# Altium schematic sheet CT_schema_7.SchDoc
size 366 x 245 mm
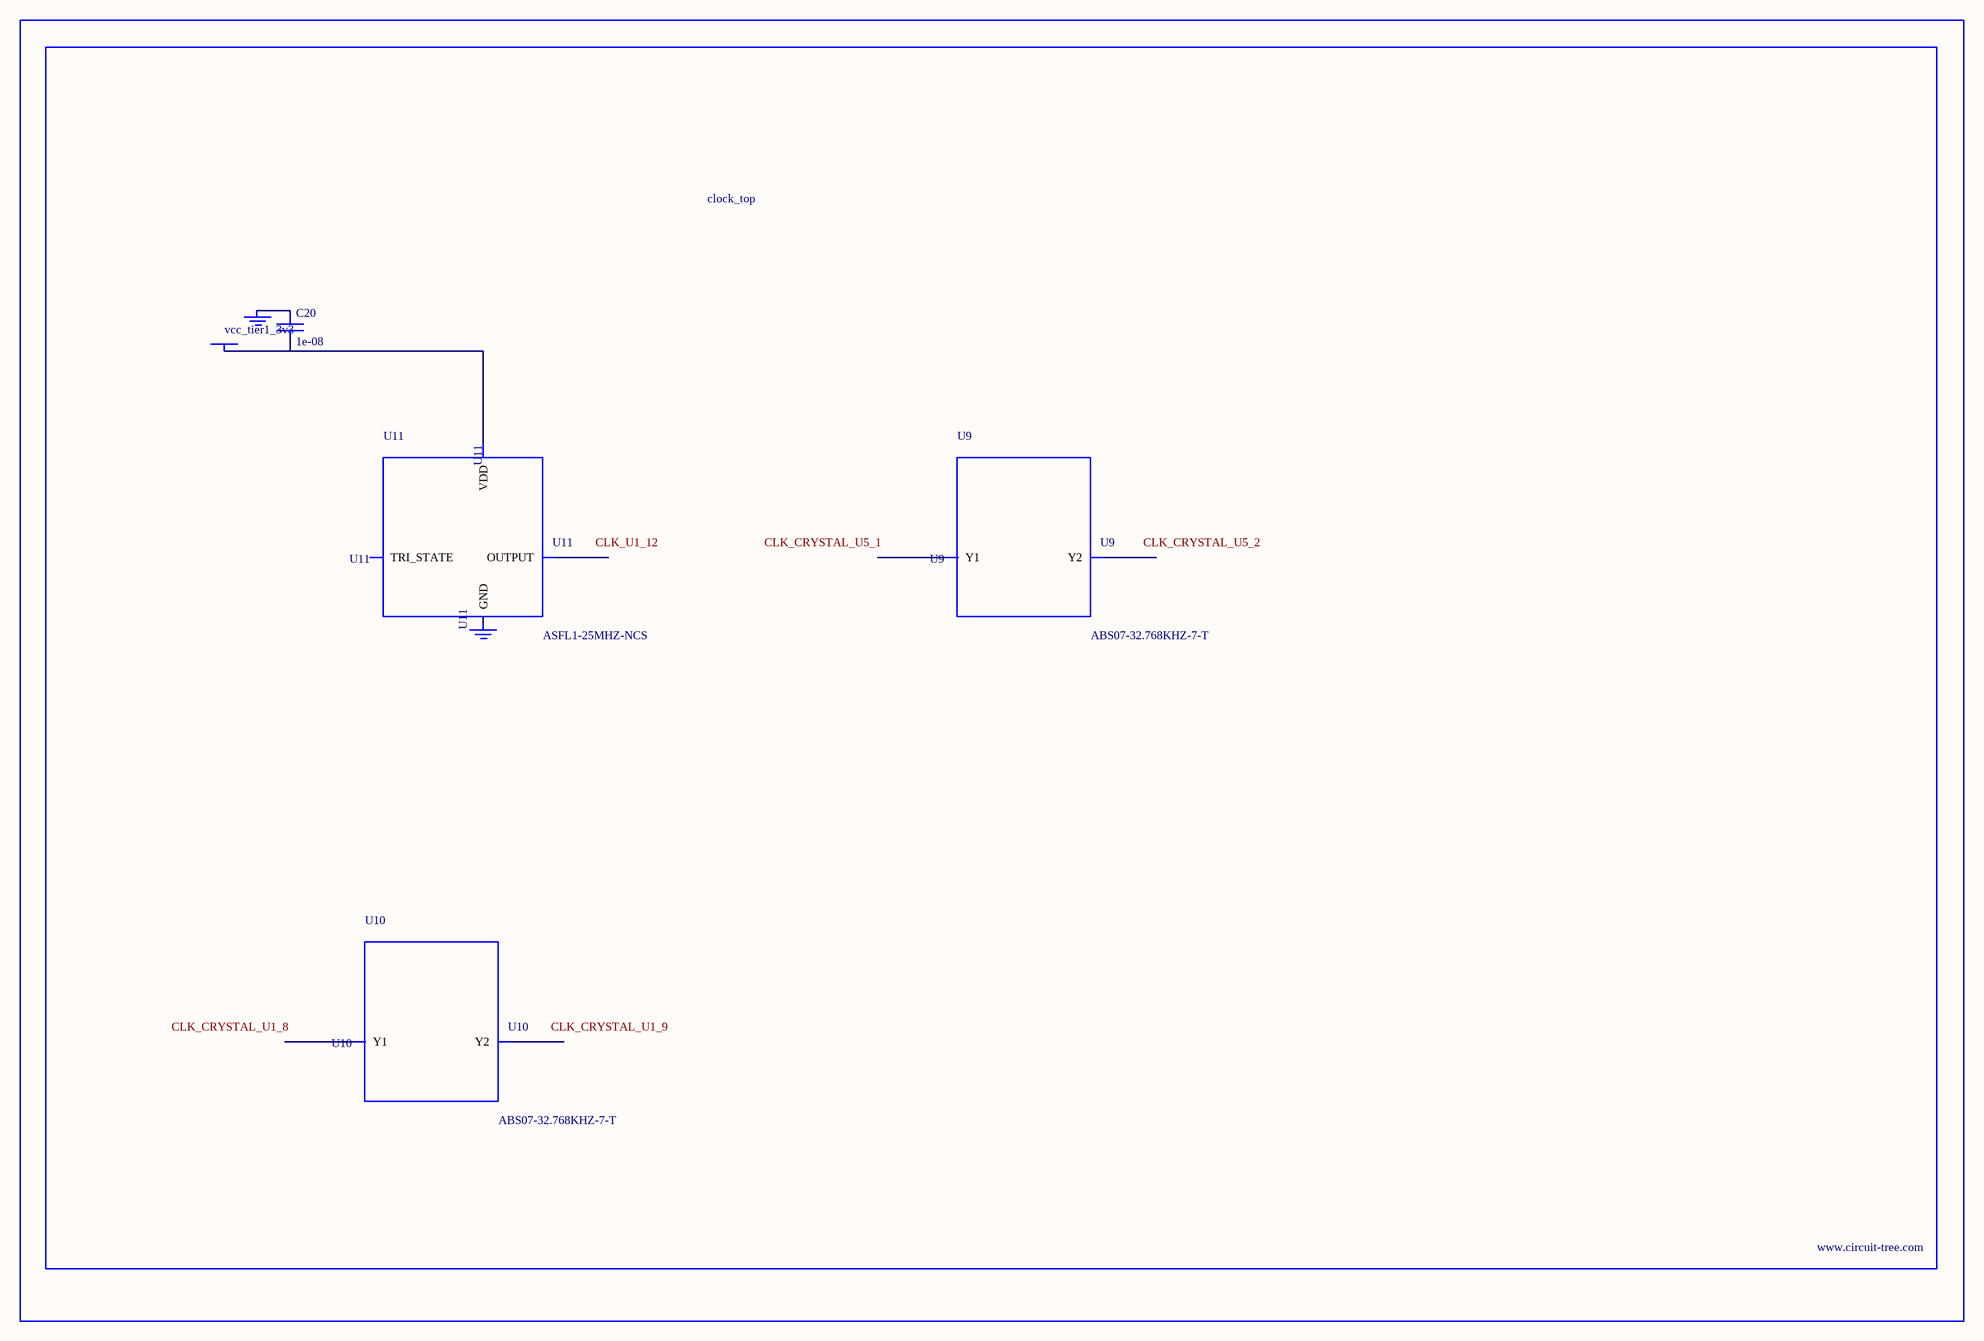
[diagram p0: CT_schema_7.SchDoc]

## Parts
BORDER6  (no value)
C20  1e-08  [C0402]
GND_INSTANCE_6_0  (no value)
GND_INSTANCE_6_1  (no value)
POWER_INSTANCE_6_0  vcc_tier1_3v3
U9  ABS07-32.768KHZ-7-T  [ABS07-32.768KHZ-7-T]
U10  ABS07-32.768KHZ-7-T  [ABS07-32.768KHZ-7-T]
U11  ASFL1-25MHZ-NCS  [ASFL1]

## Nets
NetC20_1: C20.1 GND_INSTANCE_6_0.0(GND)
NetC20_2: C20.2 POWER_INSTANCE_6_0.0(PWR) U11.4(VDD)

Not connected (* = marked no-connect by the designer): GND_INSTANCE_6_1 0(GND); U9 1(Y1) 2(Y2); U10 1(Y1) 2(Y2); U11 1(TRI_STATE) 2(GND) 3(OUTPUT)

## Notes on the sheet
- Labels drawn without touching a wire or pin: CLK_CRYSTAL_U1_8, CLK_CRYSTAL_U1_9, CLK_CRYSTAL_U5_1, CLK_CRYSTAL_U5_2, CLK_U1_12

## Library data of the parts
BORDER6 = BORDER_PAGE6
C20 = C0402C103K3RAC
GND_INSTANCE_6_0 GND_INSTANCE_6_1 = GND
POWER_INSTANCE_6_0 = PWR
